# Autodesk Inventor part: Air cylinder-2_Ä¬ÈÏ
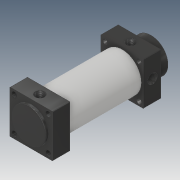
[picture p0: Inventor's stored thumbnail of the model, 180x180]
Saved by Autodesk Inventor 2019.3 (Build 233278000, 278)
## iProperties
Created: 2010-06
Part Number: Air cylinder-2_Ä¬ÈÏ
Material: Ogólny
Document SubType Name: Modeling
Designer: CADENGINEERING4
Density: 1 g/cm^3
Appearance: Gładki — czarny
Author: CADENGINEERING4
Revision Number: ÈÎºÎ
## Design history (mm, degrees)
feature "NONE"
node "Bryła1"
